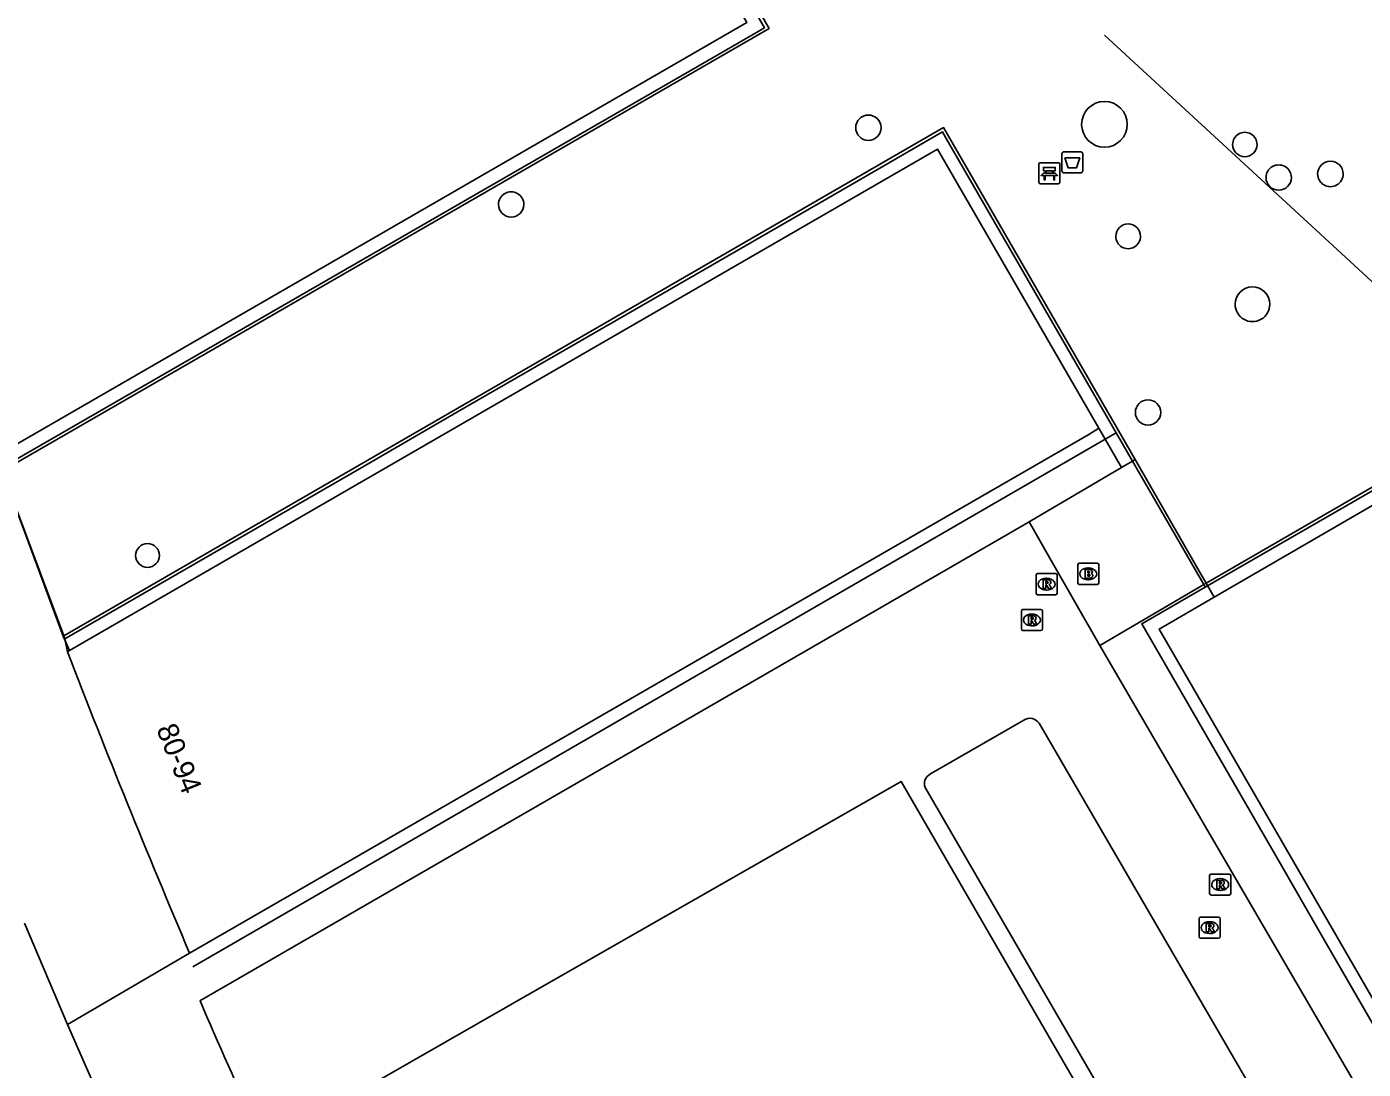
# Model space of a CAD drawing. Extents: x 155018 to 156648, y 383980 to 385733.
# Drawn here: x 155915.4 to 155978.8, y 384943.1 to 384992.6 of the extents above; entities that cross this region are included whole.
import ezdxf

# ---------------------------------------------------------------- set-up
doc = ezdxf.new("R2010")
doc.units = 0
for name, color, linetype in [('IMGEO_Afvalbak', 7, 'Continuous'), ('IMGEO_Bank', 7, 'Continuous'), ('IMGEO_Brandkraan', 7, 'Continuous'), ('IMGEO_Lijnafwatering', 7, 'Continuous'), ('IMGEO_Pand', 7, 'Continuous'), ('IMGEO_Pand_nummerreeks', 7, 'Continuous'), ('IMGEO_Parkeervlak_gesloten', 7, 'Continuous'), ('IMGEO_Rijbaan_lokaal_gesloten', 7, 'Continuous'), ('IMGEO_Rioolput', 7, 'Continuous'), ('IMGEO_Voetpad_gesloten', 7, 'Continuous'), ('IMGEO_Voetpad_open', 7, 'Continuous')]:
    doc.layers.add(name, color=color, linetype=linetype)

msp = doc.modelspace()

# ---------------------------------------------------------------- linework, layer by layer
at = {"layer": 'IMGEO_Afvalbak'}
for p, q in [((155964.527, 384985.738), (155964.527, 384986.538)), ((155964.527, 384986.538), (155964.527, 384985.738)), ((155964.627, 384986.638), (155965.417, 384986.638)), ((155965.417, 384986.638), (155964.627, 384986.638)), ((155965.517, 384986.538), (155965.517, 384985.738)), ((155965.517, 384985.738), (155965.517, 384986.538)), ((155965.417, 384985.638), (155964.627, 384985.638)), ((155964.627, 384985.638), (155965.417, 384985.638))]:
    msp.add_line(p, q, dxfattribs=at)
msp.add_lwpolyline([(155964.67, 384986.352), (155965.374, 384986.352), (155965.225, 384985.882), (155964.819, 384985.882), (155964.67, 384986.352)], dxfattribs=at)
for centre, start, end in [((155964.627, 384986.538), 90, 180), ((155964.627, 384986.538), 90, 180), ((155965.417, 384986.538), 0, 90), ((155965.417, 384986.538), 360, 90), ((155964.627, 384985.738), 180, 270), ((155964.627, 384985.738), 180, 270), ((155965.417, 384985.738), 270, 0), ((155965.417, 384985.738), 270, 0)]:
    msp.add_arc(centre, 0.1, start, end, dxfattribs=at)
at = {"layer": 'IMGEO_Bank'}
for p, q in [((155963.432, 384985.195), (155963.432, 384986.036)), ((155963.432, 384986.036), (155963.432, 384985.195)), ((155963.507, 384986.12), (155964.348, 384986.12)), ((155964.348, 384986.12), (155963.507, 384986.12)), ((155963.741, 384985.626), (155963.741, 384985.732)), ((155963.785, 384985.732), (155963.785, 384985.626)), ((155964.073, 384985.738), (155963.791, 384985.738)), ((155963.791, 384985.62), (155964.073, 384985.62)), ((155964.079, 384985.626), (155964.079, 384985.732)), ((155964.123, 384985.732), (155964.123, 384985.626)), ((155964.432, 384986.045), (155964.432, 384985.204)), ((155964.432, 384985.204), (155964.432, 384986.045)), ((155964.357, 384985.12), (155963.516, 384985.12)), ((155963.516, 384985.12), (155964.357, 384985.12)), ((155964.129, 384985.518), (155963.736, 384985.518))]:
    msp.add_line(p, q, dxfattribs=at)
for points in [[(155963.679, 384985.518), (155963.537, 384985.518), (155963.649, 384985.62), (155963.735, 384985.62)], [(155963.735, 384985.738), (155963.649, 384985.738), (155963.649, 384985.899), (155964.212, 384985.899), (155964.212, 384985.738), (155964.129, 384985.738)], [(155964.129, 384985.62), (155964.212, 384985.62), (155964.324, 384985.518), (155964.185, 384985.518)], [(155963.729, 384985.511), (155963.729, 384985.304), (155963.686, 384985.304), (155963.686, 384985.511)], [(155964.179, 384985.511), (155964.179, 384985.304), (155964.135, 384985.304), (155964.135, 384985.511)]]:
    msp.add_lwpolyline(points, dxfattribs=at)
for centre, radius, start, end in [((155963.51, 384986.042), 0.0779, 92.4484, 184.28452), ((155963.51, 384986.042), 0.0779, 92.4484, 184.28452), ((155963.734, 384985.731), 0.00671, 2.89567, 87.10433), ((155963.734, 384985.627), 0.00671, 272.89567, 357.10433), ((155963.791, 384985.731), 0.00671, 92.89567, 177.10433), ((155963.791, 384985.627), 0.00671, 182.89567, 267.10433), ((155964.073, 384985.731), 0.00671, 2.89567, 87.10433), ((155964.073, 384985.627), 0.00671, 272.89567, 357.10433), ((155964.13, 384985.731), 0.00671, 92.89567, 177.10433), ((155964.13, 384985.627), 0.00671, 182.89567, 267.10433), ((155964.354, 384986.042), 0.0779, 2.4484, 94.28452), ((155964.354, 384986.042), 0.0779, 2.4484, 94.28452), ((155963.51, 384985.198), 0.0779, 182.4484, 274.28452), ((155963.51, 384985.198), 0.0779, 182.4484, 274.28452), ((155963.679, 384985.511), 0.00671, 2.89567, 87.10433), ((155963.736, 384985.511), 0.00671, 92.89567, 177.10433), ((155964.128, 384985.511), 0.00671, 2.89567, 87.10433), ((155964.185, 384985.511), 0.00671, 92.89567, 177.10433), ((155964.354, 384985.198), 0.0779, 272.4484, 4.28452), ((155964.354, 384985.198), 0.0779, 272.4484, 4.28452)]:
    msp.add_arc(centre, radius, start, end, dxfattribs=at)
at = {"layer": 'IMGEO_Brandkraan'}
for p, q in [((155965.275, 384966.188), (155965.275, 384967.04)), ((155965.35, 384967.114), (155966.202, 384967.114)), ((155965.763, 384966.894), (155965.788, 384966.894)), ((155966.276, 384967.04), (155966.276, 384966.188)), ((155966.202, 384966.114), (155965.35, 384966.114)), ((155965.786, 384966.334), (155965.761, 384966.334))]:
    msp.add_line(p, q, dxfattribs=at)
for points in [[(155965.275, 384966.188), (155965.275, 384967.04)], [(155965.35, 384967.114), (155966.202, 384967.114)], [(155965.623, 384966.814), (155965.623, 384966.414), (155965.836, 384966.414)], [(155965.854, 384966.814), (155965.623, 384966.814)], [(155965.802, 384966.733), (155965.748, 384966.733), (155965.748, 384966.657)], [(155965.748, 384966.657), (155965.801, 384966.657)], [(155966.276, 384967.04), (155966.276, 384966.188)], [(155966.202, 384966.114), (155965.35, 384966.114)], [(155965.81, 384966.581), (155965.748, 384966.581), (155965.748, 384966.5)], [(155965.748, 384966.5), (155965.81, 384966.5)]]:
    msp.add_lwpolyline(points, dxfattribs=at)
for centre, radius, start, end in [((155965.352, 384967.038), 0.0765, 91.55205, 178.44795), ((155965.352, 384967.038), 0.0765, 91.55205, 178.44795), ((155965.803, 384966.695), 0.0379, 267.82845, 90.93552), ((155965.858, 384966.669), 0.145, 59.4692, 91.53667), ((155965.883, 384966.716), 0.0922, 285.51372, 58.15012), ((155965.888, 384966.524), 0.105, 301.31148, 78.98903), ((155966.2, 384967.038), 0.0765, 1.55205, 88.44795), ((155966.2, 384967.038), 0.0765, 1.55205, 88.44795), ((155965.352, 384966.19), 0.0765, 181.55205, 268.44795), ((155965.352, 384966.19), 0.0765, 181.55205, 268.44795), ((155965.811, 384966.54), 0.0404, 269.87594, 90.50774), ((155965.842, 384966.665), 0.251, 268.66757, 293.53466), ((155966.2, 384966.19), 0.0765, 271.55205, 358.44795), ((155966.2, 384966.19), 0.0765, 271.55205, 358.44795)]:
    msp.add_arc(centre, radius, start, end, dxfattribs=at)
for centre, major_axis, ratio, start_param, end_param in [((155965.762, 384966.614), (-0.387, 0.002), 0.722429, 4.712389, 7.853982), ((155965.787, 384966.614), (-0.39, 0.002), 0.717154, 1.570796, 4.712389)]:
    msp.add_ellipse(centre, major_axis=major_axis, ratio=ratio, start_param=start_param, end_param=end_param, dxfattribs=at)
at = {"layer": 'IMGEO_Lijnafwatering'}
for points in [[(155941.58, 385007.853), (155950.419, 384992.525), (155948.606, 384991.48)], [(155979.805, 384979.966), (155966.546, 384992.179)], [(155948.606, 384991.48), (155931.464, 384981.596)], [(155954.496, 384985.063), (155958.853, 384987.58), (155959.028, 384987.277), (155967.101, 384973.298)], [(155935.859, 384974.296), (155945.178, 384979.68), (155954.496, 384985.063)], [(155931.464, 384981.596), (155914.323, 384971.713)], [(155971.328, 384965.984), (155984.235, 384973.428), (155990.688, 384977.149)], [(155917.222, 384963.529), (155931.2, 384971.604), (155935.859, 384974.296)], [(155957.375, 384967.675), (155967.101, 384973.298), (155967.874, 384971.96), (155971.253, 384966.114), (155971.328, 384965.984)], [(155917.445, 384962.973), (155917.143, 384963.662), (155914.255, 384971.489), (155913.964, 384972.207)], [(155940.335, 384957.824), (155952.499, 384964.856), (155957.375, 384967.675)], [(155971.328, 384965.984), (155968.314, 384964.249), (155974.89, 384952.857), (155976.969, 384949.257)], [(155923.296, 384947.973), (155937.898, 384956.415), (155940.335, 384957.824)], [(155976.969, 384949.257), (155983.206, 384938.454), (155987.363, 384931.252)]]:
    msp.add_lwpolyline(points, dxfattribs=at)
at = {"layer": 'IMGEO_Pand'}
for points in [[(155902.475, 385008.1), (155931.167, 385024.688), (155949.576, 384992.767), (155913.964, 384972.207)], [(155917.347, 384962.917), (155917.445, 384962.973), (155958.623, 384986.76), (155966.277, 384973.523)], [(155966.277, 384973.523), (155965.795, 384973.232), (155923.141, 384948.617)], [(155980.785, 384970.743), (155971.756, 384965.511)], [(155971.756, 384965.511), (155969.134, 384963.992), (155991.187, 384925.849)], [(155958.297, 384957.12), (155962.712, 384959.679)], [(155963.443, 384959.525), (155973.739, 384941.814)], [(155968.279, 384938.805), (155958.037, 384956.474)]]:
    msp.add_lwpolyline(points, dxfattribs=at)
for centre, radius, start, end in [((156347.004, 385128.679), 460.523, 201.0967, 203.01641), ((155962.997, 384959.222), 0.539, 34.24456, 121.96233), ((155958.503, 384956.662), 0.502, 114.21008, 201.94264)]:
    msp.add_arc(centre, radius, start, end, dxfattribs=at)
at = {"layer": 'IMGEO_Parkeervlak_gesloten'}
msp.add_lwpolyline([(155970.829, 384923.546), (155969.356, 384924.492), (155968.552, 384925.897), (155973.194, 384928.631), (155956.893, 384956.764), (155938.438, 384946.207), (155928.999, 384940.799), (155945.318, 384912.45), (155950.245, 384915.182), (155951.149, 384913.415), (155950.99, 384911.918)], dxfattribs=at)
at = {"layer": 'IMGEO_Rijbaan_lokaal_gesloten'}
for points in [[(155917.342, 384945.228), (155915.309, 384950.036)], [(155922.901, 384932.711), (155919.991, 384939.269), (155918.255, 384943.175), (155917.342, 384945.228)]]:
    msp.add_lwpolyline(points, dxfattribs=at)
at = {"layer": 'IMGEO_Rioolput'}
for p, q in [((155963.374, 384966.626), (155964.226, 384966.626)), ((155963.299, 384965.7), (155963.299, 384966.552)), ((155963.787, 384966.406), (155963.812, 384966.406)), ((155964.3, 384966.552), (155964.3, 384965.7)), ((155964.226, 384965.626), (155963.374, 384965.626)), ((155963.81, 384965.846), (155963.785, 384965.846)), ((155962.602, 384964), (155962.602, 384964.852)), ((155962.677, 384964.926), (155963.529, 384964.926)), ((155963.09, 384964.706), (155963.115, 384964.706)), ((155963.603, 384964.852), (155963.603, 384964)), ((155963.113, 384964.146), (155963.088, 384964.146)), ((155963.529, 384963.926), (155962.677, 384963.926)), ((155971.533, 384951.447), (155971.533, 384952.299)), ((155971.608, 384952.373), (155972.46, 384952.373)), ((155972.021, 384952.153), (155972.046, 384952.153)), ((155972.534, 384952.299), (155972.534, 384951.447)), ((155972.46, 384951.373), (155971.608, 384951.373)), ((155972.044, 384951.593), (155972.019, 384951.593)), ((155971.033, 384949.402), (155971.033, 384950.254)), ((155971.108, 384950.328), (155971.96, 384950.328)), ((155971.521, 384950.108), (155971.546, 384950.108)), ((155972.034, 384950.254), (155972.034, 384949.402)), ((155971.544, 384949.548), (155971.519, 384949.548)), ((155971.96, 384949.328), (155971.108, 384949.328))]:
    msp.add_line(p, q, dxfattribs=at)
for points in [[(155963.374, 384966.626), (155964.226, 384966.626)], [(155963.299, 384965.7), (155963.299, 384966.552)], [(155963.888, 384966.324), (155963.636, 384966.326), (155963.636, 384965.926)], [(155963.636, 384965.926), (155963.76, 384965.926), (155963.76, 384966.088), (155963.771, 384966.088)], [(155963.814, 384966.245), (155963.76, 384966.245), (155963.76, 384966.164)], [(155963.76, 384966.164), (155963.812, 384966.164)], [(155963.818, 384966.059), (155963.889, 384965.926), (155964.029, 384965.926), (155963.964, 384966.052)], [(155964.3, 384966.552), (155964.3, 384965.7)], [(155964.226, 384965.626), (155963.374, 384965.626)], [(155962.602, 384964), (155962.602, 384964.852)], [(155962.677, 384964.926), (155963.529, 384964.926)], [(155963.603, 384964.852), (155963.603, 384964)], [(155963.191, 384964.624), (155962.939, 384964.626), (155962.939, 384964.226)], [(155962.939, 384964.226), (155963.063, 384964.226), (155963.063, 384964.388), (155963.074, 384964.388)], [(155963.117, 384964.545), (155963.063, 384964.545), (155963.063, 384964.464)], [(155963.063, 384964.464), (155963.115, 384964.464)], [(155963.121, 384964.359), (155963.192, 384964.226), (155963.332, 384964.226), (155963.267, 384964.352)], [(155963.529, 384963.926), (155962.677, 384963.926)], [(155971.533, 384951.447), (155971.533, 384952.299)], [(155971.608, 384952.373), (155972.46, 384952.373)], [(155972.122, 384952.071), (155971.87, 384952.073), (155971.87, 384951.673)], [(155972.534, 384952.299), (155972.534, 384951.447)], [(155972.46, 384951.373), (155971.608, 384951.373)], [(155971.87, 384951.673), (155971.994, 384951.673), (155971.994, 384951.835), (155972.005, 384951.835)], [(155972.048, 384951.992), (155971.994, 384951.992), (155971.994, 384951.911)], [(155971.994, 384951.911), (155972.046, 384951.911)], [(155972.052, 384951.806), (155972.123, 384951.673), (155972.263, 384951.673), (155972.198, 384951.799)], [(155971.033, 384949.402), (155971.033, 384950.254)], [(155971.108, 384950.328), (155971.96, 384950.328)], [(155972.034, 384950.254), (155972.034, 384949.402)], [(155971.622, 384950.026), (155971.37, 384950.028), (155971.37, 384949.628)], [(155971.37, 384949.628), (155971.494, 384949.628), (155971.494, 384949.79), (155971.505, 384949.79)], [(155971.548, 384949.947), (155971.494, 384949.947), (155971.494, 384949.866)], [(155971.494, 384949.866), (155971.546, 384949.866)], [(155971.552, 384949.761), (155971.623, 384949.628), (155971.763, 384949.628), (155971.698, 384949.754)], [(155971.96, 384949.328), (155971.108, 384949.328)]]:
    msp.add_lwpolyline(points, dxfattribs=at)
for centre, radius, start, end in [((155963.376, 384966.55), 0.0765, 91.55205, 178.44795), ((155963.376, 384966.55), 0.0765, 91.55205, 178.44795), ((155964.224, 384966.55), 0.0765, 1.55205, 88.44795), ((155964.224, 384966.55), 0.0765, 1.55205, 88.44795), ((155963.77, 384966.035), 0.0533, 26.02933, 88.69889), ((155963.796, 384966.353), 0.19, 274.7715, 282.96867), ((155963.82, 384966.149), 0.0964, 77.00612, 93.18647), ((155963.834, 384966.206), 0.0378, 276.66336, 79.67722), ((155963.887, 384966.214), 0.109, 350.36119, 89.41601), ((155963.885, 384966.214), 0.112, 277.58423, 350.98172), ((155963.869, 384965.999), 0.108, 29.51342, 73.79051), ((155963.376, 384965.702), 0.0765, 181.55205, 268.44795), ((155963.376, 384965.702), 0.0765, 181.55205, 268.44795), ((155964.224, 384965.702), 0.0765, 271.55205, 358.44795), ((155964.224, 384965.702), 0.0765, 271.55205, 358.44795), ((155962.679, 384964.85), 0.0765, 91.55205, 178.44795), ((155962.679, 384964.85), 0.0765, 91.55205, 178.44795), ((155963.527, 384964.85), 0.0765, 1.55205, 88.44795), ((155963.527, 384964.85), 0.0765, 1.55205, 88.44795), ((155963.073, 384964.335), 0.0533, 26.02933, 88.69889), ((155963.099, 384964.653), 0.19, 274.7715, 282.96867), ((155963.123, 384964.449), 0.0964, 77.00612, 93.18647), ((155963.137, 384964.506), 0.0378, 276.66336, 79.67722), ((155963.19, 384964.514), 0.109, 350.36119, 89.41601), ((155963.188, 384964.514), 0.112, 277.58423, 350.98172), ((155963.172, 384964.299), 0.108, 29.51342, 73.79051), ((155962.679, 384964.002), 0.0765, 181.55205, 268.44795), ((155962.679, 384964.002), 0.0765, 181.55205, 268.44795), ((155963.527, 384964.002), 0.0765, 271.55205, 358.44795), ((155963.527, 384964.002), 0.0765, 271.55205, 358.44795), ((155971.61, 384952.297), 0.0765, 91.55205, 178.44795), ((155971.61, 384952.297), 0.0765, 91.55205, 178.44795), ((155972.121, 384951.961), 0.109, 350.36119, 89.41601), ((155972.458, 384952.297), 0.0765, 1.55205, 88.44795), ((155972.458, 384952.297), 0.0765, 1.55205, 88.44795), ((155971.61, 384951.449), 0.0765, 181.55205, 268.44795), ((155971.61, 384951.449), 0.0765, 181.55205, 268.44795), ((155972.004, 384951.782), 0.0533, 26.02933, 88.69889), ((155972.03, 384952.1), 0.19, 274.7715, 282.96867), ((155972.054, 384951.896), 0.0964, 77.00612, 93.18647), ((155972.068, 384951.953), 0.0378, 276.66336, 79.67722), ((155972.119, 384951.961), 0.112, 277.58423, 350.98172), ((155972.103, 384951.746), 0.108, 29.51342, 73.79051), ((155972.458, 384951.449), 0.0765, 271.55205, 358.44795), ((155972.458, 384951.449), 0.0765, 271.55205, 358.44795), ((155971.11, 384950.252), 0.0765, 91.55205, 178.44795), ((155971.11, 384950.252), 0.0765, 91.55205, 178.44795), ((155971.958, 384950.252), 0.0765, 1.55205, 88.44795), ((155971.958, 384950.252), 0.0765, 1.55205, 88.44795), ((155971.504, 384949.737), 0.0533, 26.02933, 88.69889), ((155971.53, 384950.055), 0.19, 274.7715, 282.96867), ((155971.554, 384949.851), 0.0964, 77.00612, 93.18647), ((155971.568, 384949.908), 0.0378, 276.66336, 79.67722), ((155971.621, 384949.916), 0.109, 350.36119, 89.41601), ((155971.619, 384949.916), 0.112, 277.58423, 350.98172), ((155971.603, 384949.701), 0.108, 29.51342, 73.79051), ((155971.11, 384949.404), 0.0765, 181.55205, 268.44795), ((155971.11, 384949.404), 0.0765, 181.55205, 268.44795), ((155971.958, 384949.404), 0.0765, 271.55205, 358.44795), ((155971.958, 384949.404), 0.0765, 271.55205, 358.44795)]:
    msp.add_arc(centre, radius, start, end, dxfattribs=at)
for centre, major_axis, ratio, start_param, end_param in [((155963.786, 384966.126), (-0.387, 0.002), 0.722429, 4.712389, 7.853982), ((155963.811, 384966.126), (-0.39, 0.002), 0.717154, 1.570796, 4.712389), ((155963.089, 384964.426), (-0.387, 0.002), 0.722429, 4.712389, 7.853982), ((155963.114, 384964.426), (-0.39, 0.002), 0.717154, 1.570796, 4.712389), ((155972.02, 384951.873), (-0.387, 0.002), 0.722429, 4.712389, 7.853982), ((155972.045, 384951.873), (-0.39, 0.002), 0.717154, 1.570796, 4.712389), ((155971.52, 384949.828), (-0.387, 0.002), 0.722429, 4.712389, 7.853982), ((155971.545, 384949.828), (-0.39, 0.002), 0.717154, 1.570796, 4.712389)]:
    msp.add_ellipse(centre, major_axis=major_axis, ratio=ratio, start_param=start_param, end_param=end_param, dxfattribs=at)
at = {"layer": 'IMGEO_Voetpad_gesloten'}
for points in [[(155914.251, 384971.5), (155914.373, 384971.571), (155938.439, 384985.458), (155950.631, 384992.493), (155942.064, 385007.325), (155931.817, 385025.064), (155955.448, 385038.728), (155958.02, 385040.155), (155958.285, 385040.332), (155957.893, 385040.987)], [(155968.004, 384972.037), (155958.91, 384987.786), (155917.172, 384963.671)], [(156005.259, 384985.766), (155987.127, 384975.286), (155971.372, 384966.18)], [(155966.277, 384973.523), (155967.357, 384971.656)], [(155967.357, 384971.656), (155967.874, 384971.96), (155968.004, 384972.037)], [(155971.372, 384966.18), (155970.981, 384966.859), (155968.004, 384972.037)], [(155917.172, 384963.671), (155914.251, 384971.5)], [(155971.756, 384965.511), (155971.372, 384966.18)], [(155917.172, 384963.671), (155917.222, 384963.529), (155917.347, 384962.917)]]:
    msp.add_lwpolyline(points, dxfattribs=at)
for centre, radius, start, end in [((155966.544, 384987.941), 1.085, 0, 180), ((155955.344, 384987.783), 0.601, 0, 180), ((155955.344, 384987.783), 0.601, 180, 0), ((155966.544, 384987.941), 1.085, 180, 0), ((155973.204, 384986.985), 0.579, 359.95048, 180.04952), ((155973.204, 384986.985), 0.579, 180.04952, 359.95048), ((155974.81, 384985.417), 0.601, 359.95229, 180.04771), ((155977.265, 384985.589), 0.606, 0.09463, 179.90537), ((155974.81, 384985.417), 0.601, 180.04771, 359.95229), ((155977.265, 384985.589), 0.606, 179.90553, 0.09447), ((155938.397, 384984.139), 0.599, 359.95213, 180.04787), ((155938.397, 384984.139), 0.599, 180.04787, 359.95213), ((155967.666, 384982.628), 0.586, 0.04893, 179.95107), ((155967.666, 384982.628), 0.586, 179.95107, 0.04893), ((155973.565, 384979.404), 0.823, 0.03483, 179.96517), ((155973.565, 384979.404), 0.823, 179.96517, 0.03483), ((155968.612, 384974.272), 0.6, 0, 180), ((155968.612, 384974.273), 0.6, 180.09557, 359.90443), ((155921.147, 384967.488), 0.565, 0, 180), ((155921.147, 384967.488), 0.565, 180, 0)]:
    msp.add_arc(centre, radius, start, end, dxfattribs=at)
at = {"layer": 'IMGEO_Voetpad_open'}
for points in [[(155967.357, 384971.656), (155962.977, 384969.078)], [(155923.635, 384946.357), (155961.996, 384968.511), (155962.977, 384969.078)], [(155962.977, 384969.078), (155963.831, 384967.581), (155966.32, 384963.216)], [(155966.32, 384963.216), (155971.253, 384966.114), (155971.372, 384966.18)], [(155966.32, 384963.216), (155978.685, 384941.986)], [(155917.342, 384945.228), (155923.141, 384948.617)]]:
    msp.add_lwpolyline(points, dxfattribs=at)
msp.add_arc((156213.285, 385071.332), 315.461, 203.33863, 205.75725, dxfattribs=at)

# ---------------------------------------------------------------- texts
at = {"layer": 'IMGEO_Pand_nummerreeks'}
msp.add_text('80-94', height=1, rotation=292.05654, dxfattribs=at).set_placement((155921.548, 384959.258))

doc.saveas('drawing.dxf')
